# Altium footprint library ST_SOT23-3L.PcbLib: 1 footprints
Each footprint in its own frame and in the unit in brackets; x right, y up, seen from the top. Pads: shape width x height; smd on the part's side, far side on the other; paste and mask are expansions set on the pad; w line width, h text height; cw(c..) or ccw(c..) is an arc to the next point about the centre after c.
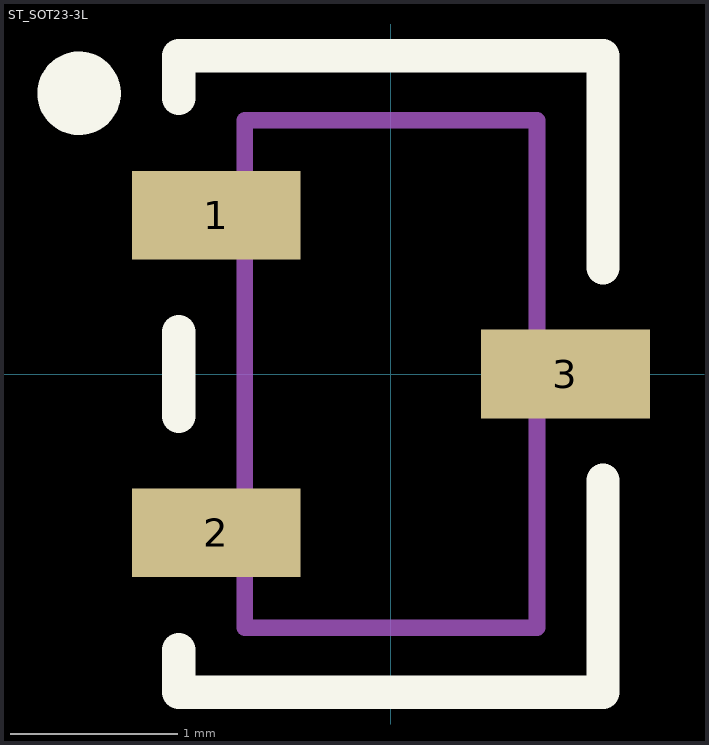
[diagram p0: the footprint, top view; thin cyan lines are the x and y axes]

## ST_SOT23-3L [mm]
height 1.25
pads (3):
  rect 1.01x0.53 smd: 1(-1.045,0.95) 2(-1.045,-0.95) 3(1.045,0)
Top Overlay:
  circle w0.25: c-1.867,1.68 r0.125
  lines w0.2: -1.27,-1.651 -1.27,-1.905 1.27,-1.905 1.27,-0.635 ; -1.27,-0.254 -1.27,0.254 ; -1.27,1.651 -1.27,1.905 1.27,1.905 1.27,0.635
Mechanical 13:
  lines w0.1: -0.875,-1.52 0.875,-1.52 0.875,1.52 -0.875,1.52 -0.875,-1.52
3D body "ST_SOT23-3L.step": height 1.01, standoff -0.04, extent -1.4,-1.47 1.4,1.45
